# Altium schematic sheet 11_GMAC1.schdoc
size 302 x 215 mm; Symbol: Sheet_A4; Device: Sheet_A4; @Project Name: Avaota A1; Company: YuzukiHD; Version: 1.0; @Page No: 12; @Page Count: 13; @Update Date: 2024-02-27; Comment: GloomyGhost
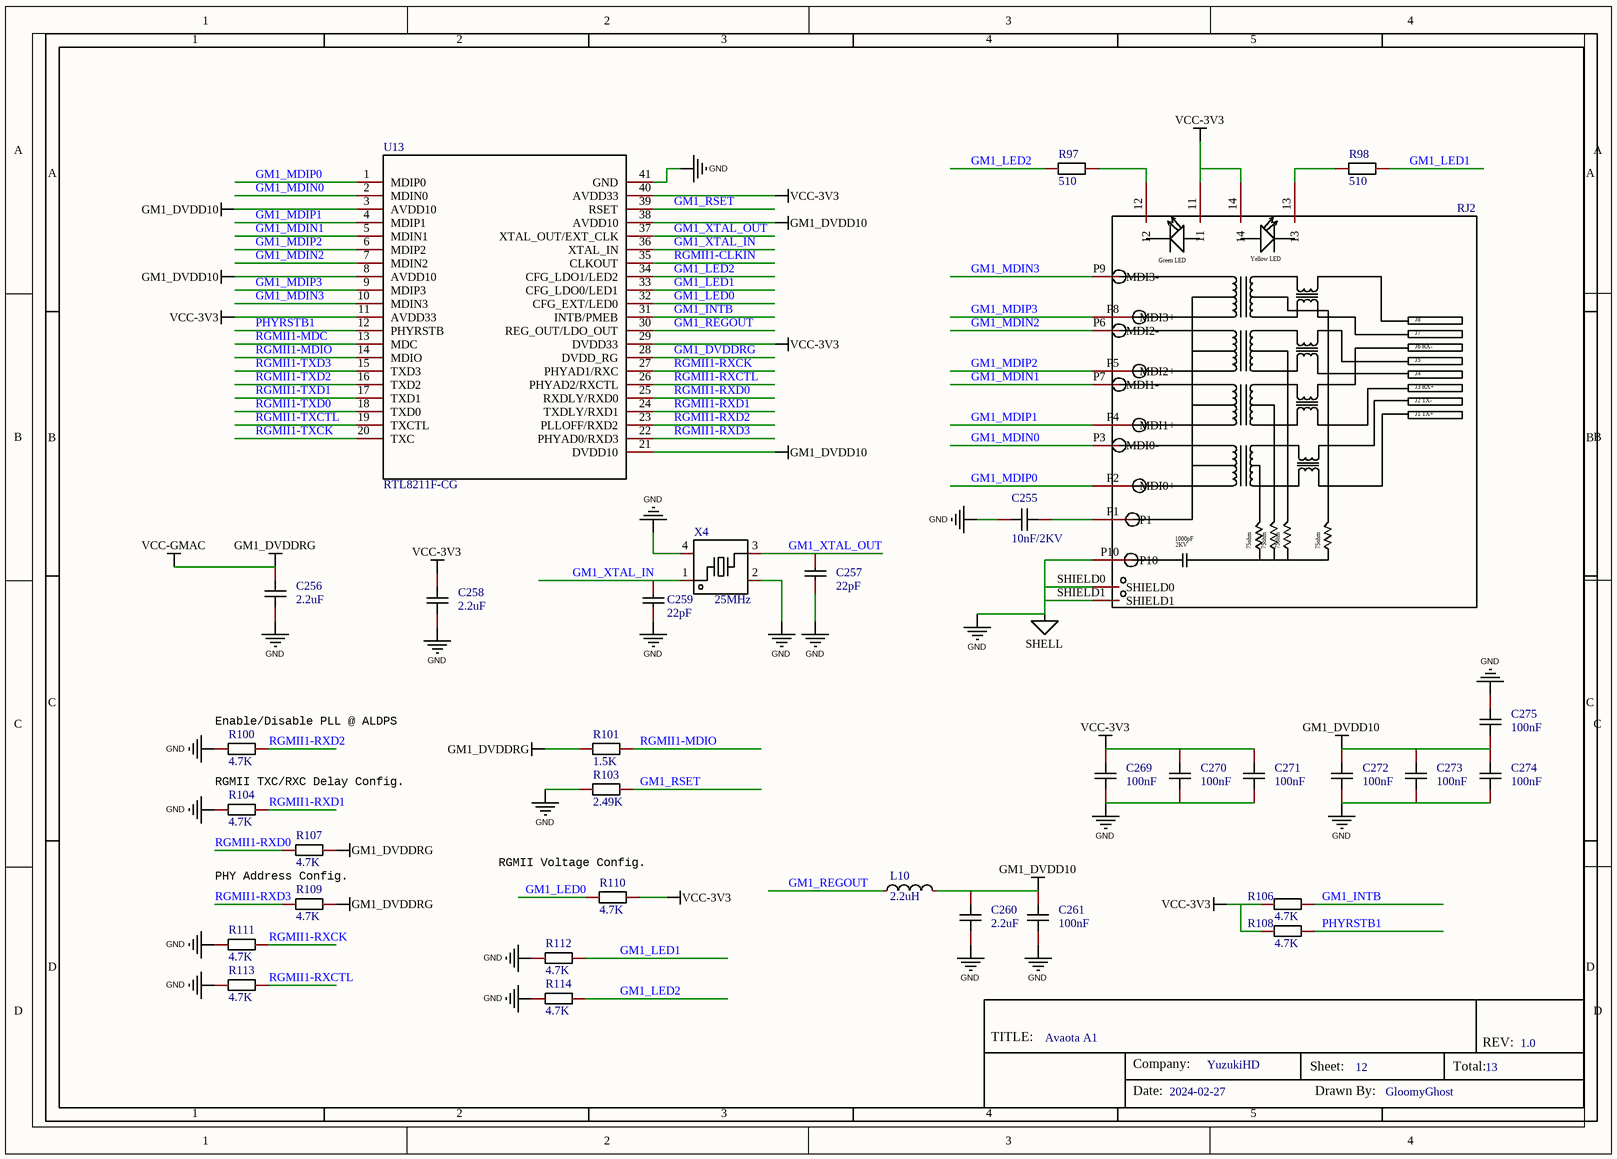
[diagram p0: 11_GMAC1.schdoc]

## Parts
C255  10nF/2KV  [C1206]
C256  2.2uF  [c0201 nsk]
C257  22pF  [c0201 nsk]
C258  2.2uF  [c0201 nsk]
C259  22pF  [c0201 nsk]
C260  2.2uF  [c0201 nsk]
C261  100nF  [c0201 nsk]
C269  100nF  [c0201 nsk]
C270  100nF  [c0201 nsk]
C271  100nF  [c0201 nsk]
C272  100nF  [c0201 nsk]
C273  100nF  [c0201 nsk]
C274  100nF  [c0201 nsk]
C275  100nF  [c0201 nsk]
L10  2.2uH  [IND-SMD_L2.0-W1.6]
R97  510  [r0201 nsk]
R98  510  [r0201 nsk]
R100  4.7K  [r0201 nsk]
R101  1.5K  [r0201 nsk]
R103  2.49K  [r0201 nsk]
R104  4.7K  [r0201 nsk]
R106  4.7K  [r0201 nsk]
R107  4.7K  [r0201 nsk]
R108  4.7K  [r0201 nsk]
R109  4.7K  [r0201 nsk]
R110  4.7K  [r0201 nsk]
R111  4.7K  [r0201 nsk]
R112  4.7K  [r0201 nsk]
R113  4.7K  [r0201 nsk]
R114  4.7K  [r0201 nsk]
RJ2  HR911130A  [RJ45-TH_HR911130A]  (value not drawn)
U13  RTL8211F-CG  [WQFN-40_L5.0-W5.0-P0.4-BL-EP]
X4  25MHz  [crystal-smd_4p-l2.0-w1.6-bl-nsk]

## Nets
GM1_DVDD10: C260.1 C261.1 C272.1 C273.1 C274.1 C275.2 L10.2 U13.3(AVDD10) U13.8(AVDD10) U13.21(DVDD10) U13.38(AVDD10)
GM1_DVDDRG: C256.1 R101.1 R107.2 R109.2 U13.28(DVDD_RG)  [also labelled VCC-GMAC]
GND: C255.1 C256.2 C257.1 C258.2 C259.1 C260.2 C261.2 C269.2 C270.2 C271.2 C272.2 C273.2 C274.2 C275.1 R100.1 R103.1 R104.1 R111.1 R112.1 R113.1 R114.1 RJ2.P10 RJ2.SHIELD0 RJ2.SHIELD1 U13.41(GND) X4.2(GND) X4.4(GND)  [also labelled SHELL]
VCC-3V3: C258.1 C269.1 C270.1 C271.1 R106.1 R108.1 R110.2 RJ2.11 RJ2.14 U13.11(AVDD33) U13.29(DVDD33) U13.40(AVDD33)
GM1_INTB: R106.2 U13.31(INTB/PMEB)
GM1_LED0: R110.1 U13.32(CFG_EXT/LED0)
GM1_LED1: R98.2 R112.2 U13.33(CFG_LDO0/LED1)
GM1_LED2: R97.1 R114.2 U13.34(CFG_LDO1/LED2)
GM1_MDIN0: RJ2.P3(MDI0-) U13.2(MDIN0)
GM1_MDIN1: RJ2.P7(MDI1-) U13.5(MDIN1)
GM1_MDIN2: RJ2.P6(MDI2-) U13.7(MDIN2)
GM1_MDIN3: RJ2.P9(MDI3-) U13.10(MDIN3)
GM1_MDIP0: RJ2.P2(MDI0+) U13.1(MDIP0)
GM1_MDIP1: RJ2.P4(MDI1+) U13.4(MDIP1)
GM1_MDIP2: RJ2.P5(MDI2+) U13.6(MDIP2)
GM1_MDIP3: RJ2.P8(MDI3+) U13.9(MDIP3)
GM1_REGOUT: L10.1 U13.30(REG_OUT/LDO_OUT)
GM1_RSET: R103.2 U13.39(RSET)
GM1_XTAL_IN: C259.2 U13.36(XTAL_IN) X4.1(IN)
GM1_XTAL_OUT: C257.2 U13.37(XTAL_OUT/EXT_CLK) X4.3(OUT)
PHYRSTB1: R108.2 U13.12(PHYRSTB)
RGMII1-CLKIN: U13.35(CLKOUT)
RGMII1-MDC: U13.13(MDC)
RGMII1-MDIO: R101.2 U13.14(MDIO)
RGMII1-RXCK: R111.2 U13.27(PHYAD1/RXC)
RGMII1-RXCTL: R113.2 U13.26(PHYAD2/RXCTL)
RGMII1-RXD0: R107.1 U13.25(RXDLY/RXD0)
RGMII1-RXD1: R104.2 U13.24(TXDLY/RXD1)
RGMII1-RXD2: R100.2 U13.23(PLLOFF/RXD2)
RGMII1-RXD3: R109.1 U13.22(PHYAD0/RXD3)
RGMII1-TXCK: U13.20(TXC)
RGMII1-TXCTL: U13.19(TXCTL)
RGMII1-TXD0: U13.18(TXD0)
RGMII1-TXD1: U13.17(TXD1)
RGMII1-TXD2: U13.16(TXD2)
RGMII1-TXD3: U13.15(TXD3)
NetC255_2: C255.2 RJ2.P1
NetR97_2: R97.2 RJ2.12
NetR98_1: R98.1 RJ2.13

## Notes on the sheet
- (near R100) Enable/Disable PLL @ ALDPS
- RGMII TXC/RXC Delay Config.
- PHY Address Config.
- (near R110) RGMII Voltage Config.

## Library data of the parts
C255 = CAP_1206: Symbol: CapAcitance; Convert to PCB: yes
C256 C258 C260 C261 C269-C275 = 0201X225M6R3NT: Manufacturer: FH(风华); Add into BOM: yes; Tolerance: ±20%; Voltage Rated: 6.3V; Temperature Coefficient: X5R; Description: 容值:2.2uF;精度:±20%;额定电压:6.3V;材质(温度系数):X5R;
C257 C259 = 0201CG220J500NT: Manufacturer: FH(风华); Add into BOM: yes; Tolerance: ±5%; Voltage Rated: 50V; Temperature Coefficient: C0G; Description: 容值:22pF;精度:±5%;额定电压:50V;材质(温度系数):C0G;
L10 = WPN252012H2R2MT: Manufacturer: Sunlord(顺络); Add into BOM: yes; Tolerance: ±20%; Rated Current: 1.9A; Saturation Current (Isat): 3A; DC Resistance (DCR): 120mΩ; Description: 电感值:2.2uH;精度:±20%;额定电流:1.9A;饱和电流(Isat):3A;类型:-;
R97 R98 R100 R101 R103 R104 R106-R114 = Res_0201: Symbol: 电阻; Convert to PCB: yes
RJ2 = HR911130A: Manufacturer: HANRUN(汉仁); Add into BOM: yes; Connector Type: RJ插座; USOC Codes: RJ45; Number of Ports: 1; LED: 有; Description: 连接器类型:RJ插座;USOC代码:RJ45;端口数量:1;等级:-;屏蔽:-;LED:有;
U13 = RTL8211F-CG: Manufacturer: REALTEK(瑞昱); Add into BOM: yes; Description: 应用功能:-;通道数:-;接口类型:-;
X4 = 7D025000Q01: Manufacturer: HD(浩都频率); Add into BOM: yes; Crystal Type: 贴片晶振; Normal temperature Frequency Tolerance: ±10ppm; External load capacitor: 18pF; Frequency Stability(Full temperature range): ±20ppm; Description: 晶振类型:贴片晶振;频率:25MHz;常温频差:±10ppm;外接负载电容:18pF;频率稳定度(全温):±20ppm;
